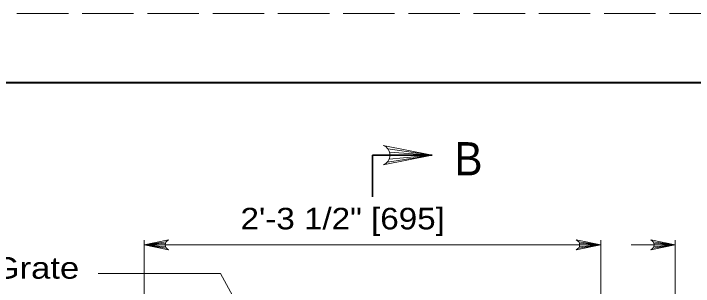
# Model space of a CAD drawing. Extents: x -410.5 to -376.5, y 1617.6 to 1661.6.
# Drawn here: x -405.643 to -400.725, y 1659.586 to 1661.562 of the extents above; entities that cross this region are included whole.
import ezdxf

# ---------------------------------------------------------------- set-up
doc = ezdxf.new("R2010")
doc.units = 0
doc.header["$LTSCALE"] = 0.062
doc.linetypes.add('LONG_DASHED', pattern=[7.5, 6, -1.5])
doc.layers.add('1', color=7, linetype='Continuous', lineweight=13)

msp = doc.modelspace()

# ---------------------------------------------------------------- linework, layer by layer
at = {"layer": '1', "lineweight": 25}
msp.add_line((-408.45475, 1661.06183), (-376.95475, 1661.06183), dxfattribs=at)
at = {"layer": '1'}
for p, q in [((-402.93492, 1660.5815), (-402.61442, 1660.53667)), ((-402.92408, 1660.55933), (-402.61442, 1660.53667)), ((-402.93875, 1660.48708), (-402.61442, 1660.53667)), ((-402.92642, 1660.50783), (-402.61442, 1660.53667)), ((-402.92075, 1660.53667), (-402.61442, 1660.53667)), ((-404.69908, 1658.80683), (-404.69908, 1659.92217)), ((-404.53883, 1659.90942), (-404.69908, 1659.887)), ((-401.55533, 1659.90942), (-401.39508, 1659.887)), ((-401.39508, 1658.80683), (-401.39508, 1659.92217)), ((-401.01667, 1659.90942), (-400.85642, 1659.887)), ((-400.85642, 1658.80683), (-400.85642, 1659.92217)), ((-404.54433, 1659.89833), (-404.69908, 1659.887)), ((-404.54592, 1659.887), (-404.69908, 1659.887)), ((-404.54308, 1659.87258), (-404.69908, 1659.887)), ((-404.537, 1659.86225), (-404.69908, 1659.887)), ((-401.55725, 1659.86225), (-401.39508, 1659.887)), ((-401.55108, 1659.87258), (-401.39508, 1659.887)), ((-401.54992, 1659.89833), (-401.39508, 1659.887)), ((-401.54825, 1659.887), (-401.39508, 1659.887)), ((-401.17475, 1659.887), (-400.85642, 1659.887)), ((-401.0185, 1659.86225), (-400.85642, 1659.887)), ((-401.01242, 1659.87258), (-400.85642, 1659.887)), ((-401.01125, 1659.89833), (-400.85642, 1659.887)), ((-401.00958, 1659.887), (-400.85642, 1659.887))]:
    msp.add_line(p, q, dxfattribs=at)
at = {"layer": '1', "lineweight": 35}
for p, q in [((-403.04708, 1660.53667), (-402.61442, 1660.53667)), ((-403.04708, 1660.23458), (-403.04708, 1660.53667))]:
    msp.add_line(p, q, dxfattribs=at)
at = {"layer": '1', "linetype": 'LONG_DASHED'}
msp.add_lwpolyline([(-410.45475, 1639.56183), (-376.45475, 1639.56183), (-376.45475, 1661.56183), (-410.45475, 1661.56183)], close=True, dxfattribs=at)
at = {"layer": '1', "lineweight": 40}
msp.add_lwpolyline([(-408.45475, 1661.06183), (-376.95475, 1661.06183), (-376.95475, 1640.06183), (-408.45475, 1640.06183)], close=True, dxfattribs=at)
msp.add_lwpolyline([(-408.45475, 1661.06183), (-376.95475, 1661.06183), (-376.95475, 1640.06183), (-408.45475, 1640.06183)], close=True, dxfattribs=at)
at = {"layer": '1'}
for points in [[(-402.96842, 1660.46583), (-402.61442, 1660.53667), (-402.96842, 1660.60742)], [(-404.52208, 1659.85158), (-404.69908, 1659.887), (-404.52208, 1659.92242)], [(-401.57208, 1659.85158), (-401.39508, 1659.887), (-401.57208, 1659.92242)], [(-401.03342, 1659.85158), (-400.85642, 1659.887), (-401.03342, 1659.92242)], [(-404.69908, 1659.887), (-402.93108, 1659.887), (-401.89233, 1659.887), (-401.39508, 1659.887)], [(-403.62667, 1658.72817), (-404.14675, 1659.67892), (-405.03058, 1659.67892)]]:
    msp.add_lwpolyline(points, dxfattribs=at)
for centre, radius, start, end in [((-402.99703, 1660.53671), 0.0764, 292.08605, 67.91218), ((-404.50782, 1659.88703), 0.0382, 112.08782, 247.91395), ((-401.58641, 1659.88703), 0.0382, 292.08605, 67.91218), ((-401.0477, 1659.88703), 0.0382, 292.08605, 67.91218)]:
    msp.add_arc(centre, radius, start, end, dxfattribs=at)

# ---------------------------------------------------------------- texts
for s, height, width, p in [('B', 0.24, 0.95, (-402.45375, 1660.39075)), ('2\'-3 1/2" [695]', 0.156, 1.15, (-404.00133, 1659.99925)), ('Grate', 0.156, 1.2, (-405.79458, 1659.64208))]:
    msp.add_text(s, height=height, dxfattribs=dict(at, width=width)).set_placement(p)

doc.saveas('drawing.dxf')
